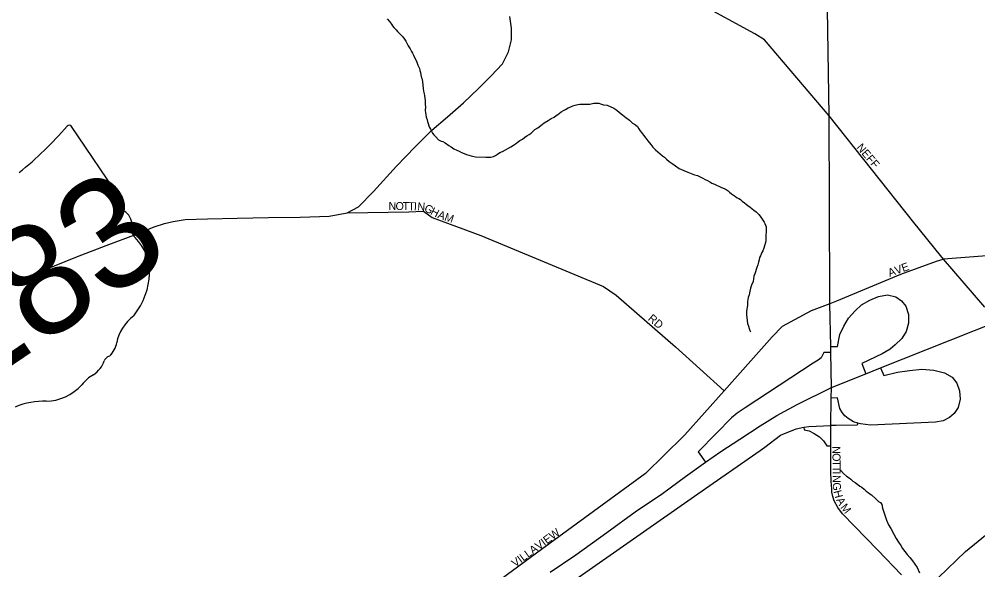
# Model space of a CAD drawing. Extents: x 2139079 to 2262683, y 1235796 to 1334992.
# Drawn here: x 2223564 to 2229551, y 1303635 to 1307072 of the extents above; entities that cross this region are included whole.
import ezdxf

# ---------------------------------------------------------------- set-up
doc = ezdxf.new("R2010")
doc.units = 0
for name, color, linetype in [('GM_X_City_Street', 7, 'Continuous'), ('GM_X_City_Street_Text', 7, 'Continuous'), ('GM_X_Interchange_Ramps', 7, 'Continuous'), ('GM_X_Interstate_Route', 7, 'Continuous'), ('GM_X_Minor_River', 7, 'Continuous'), ('GM_X_State_Route', 7, 'Continuous'), ('GM_X_State_Shield', 7, 'Continuous')]:
    doc.layers.add(name, color=color, linetype=linetype)

msp = doc.modelspace()

# ---------------------------------------------------------------- linework, layer by layer
at = {"layer": 'GM_X_City_Street'}
for points in [[(2228627.4, 1305337.6), (2228622.6, 1306468.3), (2228588, 1308737.8)], [(2229151.8, 1305804), (2228622.6, 1306468.3), (2228218.5, 1306943.9), (2228158.5, 1306979.9), (2227102.5, 1307556.5), (2226602.2, 1307841.3)], [(2231294.5, 1306314.6), (2230784.6, 1305955.9), (2230638.5, 1305853.4), (2230457.2, 1305736.7), (2230340.9, 1305675.6), (2230212.8, 1305648.7), (2229939.3, 1305624.3), (2229634.8, 1305597.1), (2229335.6, 1305573.3), (2229331.3, 1305572)], [(2225612.1, 1305864.1), (2225997.3, 1305869.4), (2226087.3, 1305872.9)], [(2226087.3, 1305872.9), (2226089.9, 1305873), (2226143.3, 1305834.3), (2226448.2, 1305722.8), (2227212.5, 1305403.8), (2227292.2, 1305349.3), (2227663.7, 1305026.1), (2227966.7, 1304753.5)], [(2229317.2, 1305596.4), (2229151.8, 1305804)], [(2229594.4, 1305274.8), (2229335.6, 1305573.3), (2229317.2, 1305596.4)], [(2229331.3, 1305572), (2229291.4, 1305560.5), (2229067, 1305477.9), (2228668.4, 1305312.9)], [(2228632.6, 1304536.4), (2228635.1, 1304707.6), (2228636.1, 1304773.8), (2228632.6, 1304992.1), (2228632, 1305028.5), (2228627.6, 1305296), (2228627.4, 1305337.6)], [(2228668.4, 1305312.9), (2228627.6, 1305296), (2228510.9, 1305252.2), (2228328.5, 1305153.2), (2228266.1, 1305089.2), (2227966.7, 1304753.5)], [(2229193.8, 1303478.3), (2229473.2, 1303749.8), (2230411, 1304512.8), (2231077.9, 1305045.6)], [(2227966.7, 1304753.5), (2227721, 1304477.4)], [(2228191, 1304380.9), (2228221.1, 1304401.9), (2228319.6, 1304475), (2228415.4, 1304514.4), (2228463.9, 1304526.7), (2228494.6, 1304530.7), (2228632.6, 1304536.4)], [(2228633.4, 1304246.7), (2228631.9, 1304320.6), (2228632.2, 1304408.5), (2228632.6, 1304536.4)], [(2227721, 1304477.4), (2227713.4, 1304468.9), (2227475.6, 1304235.7), (2226826.9, 1303762.5), (2226573.7, 1303576.5), (2226301.9, 1303399.3), (2226018.4, 1303234), (2225663.9, 1303080.5), (2225061.4, 1302832.6), (2224423.2, 1302561), (2224116.1, 1302431.2), (2223903.5, 1302360.3), (2223820.7, 1302336.7), (2223611.1, 1302336.8)], [(2224581.8, 1302339.7), (2225814.8, 1302839.9), (2226126.7, 1302972.1), (2226328.4, 1303062.8), (2226638.7, 1303296), (2227803.3, 1304110.5), (2228191, 1304380.9)], [(2228638.6, 1304139), (2228634.6, 1304188.9), (2228633.4, 1304246.7)], [(2229073.7, 1303604), (2228926.2, 1303758.5), (2228706.1, 1303984), (2228677, 1304023.6), (2228653.9, 1304065.1), (2228645, 1304093.7), (2228640.1, 1304120.2), (2228638.6, 1304139)]]:
    msp.add_lwpolyline(points, dxfattribs=at)
at = {"layer": 'GM_X_Interchange_Ramps'}
for points in [[(2228632, 1305028.5), (2228675, 1305029.6), (2228689.2, 1305103.8), (2228713.2, 1305156.8), (2228744.1, 1305206.7), (2228784.8, 1305250.8), (2228824.2, 1305288.5), (2228876.3, 1305317.7), (2228930.9, 1305340.2), (2228985.9, 1305351.4), (2229038.5, 1305338.7), (2229074.6, 1305314.1), (2229100.9, 1305280), (2229118.1, 1305229.1), (2229117.4, 1305175.2), (2229103, 1305122), (2229075.2, 1305079), (2229034.9, 1305038.9), (2229003.1, 1305011.6), (2228952.7, 1304983.1), (2228826.5, 1304922.1), (2228852.1, 1304859.6)], [(2228632.6, 1304992.1), (2228588.2, 1304991.1), (2228571.9, 1304958.2), (2228554.4, 1304943.9), (2228523.4, 1304924.6), (2228098.7, 1304645.9), (2228047.8, 1304613.3), (2228012.7, 1304584.8), (2227918, 1304488.9), (2227803.7, 1304371.7), (2227850.6, 1304307.8)], [(2228943.7, 1304896), (2228963, 1304849.2), (2229049.4, 1304868.4), (2229123.8, 1304879.2), (2229201.1, 1304887.3), (2229276.1, 1304881.1), (2229341.8, 1304863.9), (2229389.9, 1304837.9), (2229419.7, 1304799.4), (2229437.3, 1304752.5), (2229439.9, 1304699.9), (2229428.9, 1304648), (2229402.6, 1304611.3), (2229373.5, 1304586.9), (2229333.6, 1304566.1), (2229287.5, 1304556.4), (2228881.6, 1304537.4), (2228819, 1304546.2), (2228800.7, 1304551.1), (2228774.3, 1304558.1), (2228741.2, 1304580.1), (2228719.6, 1304596.8), (2228704.1, 1304617.7), (2228688.9, 1304642.6), (2228674, 1304707.8), (2228635.1, 1304707.6)], [(2228463.9, 1304526.7), (2228467.2, 1304509.3), (2228498.1, 1304502.7), (2228529, 1304487.2), (2228561.1, 1304465.1), (2228586.5, 1304439.7), (2228607.5, 1304408.8), (2228632.2, 1304408.5)], [(2228800.7, 1304551.1), (2228797.2, 1304538), (2228665.3, 1304536.7), (2228632.6, 1304536.4)]]:
    msp.add_lwpolyline(points, dxfattribs=at)
at = {"layer": 'GM_X_Interstate_Route'}
msp.add_lwpolyline([(2226880.9, 1303621.7), (2227040.4, 1303729.2), (2227233.7, 1303869), (2227411, 1303996.7), (2227582.4, 1304112.3), (2227725.8, 1304217.7), (2227850.6, 1304307.8), (2227947, 1304373.8), (2228064.6, 1304450.9), (2228192.2, 1304534), (2228295.9, 1304599), (2228421.6, 1304668.1), (2228636.1, 1304773.8), (2228852.1, 1304859.6), (2228943.7, 1304896), (2229671.9, 1305185.4)], dxfattribs=at)
at = {"layer": 'GM_X_Minor_River'}
for points in [[(2225862.6, 1307074.5), (2225877, 1307056.7), (2225889.4, 1307040.9), (2225895.6, 1307030.9)], [(2225895.6, 1307030.9), (2225903.8, 1307021.1), (2225918.2, 1307005.3), (2225926.4, 1306995.4), (2225936.7, 1306985.5), (2225947, 1306973.7), (2225959.3, 1306961.9), (2225969.6, 1306948), (2225979.9, 1306934.1), (2225994.5, 1306906.3), (2226005, 1306886.4), (2226013.3, 1306870.5), (2226019.6, 1306860.6), (2226025.9, 1306846.6), (2226032.2, 1306832.7), (2226040.5, 1306818.8), (2226046.8, 1306802.8), (2226053.2, 1306784.9), (2226063.7, 1306765), (2226066, 1306751), (2226070.2, 1306739), (2226072.5, 1306725), (2226076.9, 1306707), (2226081.1, 1306697), (2226085.8, 1306663), (2226086.3, 1306638.9), (2226088.7, 1306622.8), (2226093, 1306606.9), (2226095.3, 1306592.8), (2226097.6, 1306578.8), (2226099.9, 1306564.8), (2226100.1, 1306554.8), (2226100.4, 1306540.7), (2226100.8, 1306522.6), (2226099.1, 1306504.5), (2226101.5, 1306488.5), (2226103.7, 1306476.5), (2226106, 1306460.4), (2226112.4, 1306444.5), (2226114.6, 1306434.5), (2226118.9, 1306420.5), (2226123.2, 1306406.5), (2226127.4, 1306396.6), (2226133.7, 1306384.6), (2226140, 1306372.7), (2226146.2, 1306360.8), (2226154.5, 1306350.9), (2226166.8, 1306337.1), (2226183.2, 1306319.3), (2226199.5, 1306311.6), (2226209.6, 1306307.8), (2226223.8, 1306300), (2226248.2, 1306284.4), (2226262.5, 1306274.6), (2226278.8, 1306262.9), (2226297, 1306255.2), (2226311.2, 1306247.4), (2226327.4, 1306239.7), (2226343.6, 1306234), (2226357.8, 1306228.3), (2226371.9, 1306222.5), (2226386.1, 1306218.8), (2226396.2, 1306216.9), (2226414.3, 1306213.3), (2226478.6, 1306210.5), (2226496.7, 1306210.8), (2226510.7, 1306211.1), (2226526.7, 1306215.4), (2226538.6, 1306221.7), (2226550.5, 1306230), (2226566.4, 1306240.3), (2226582.3, 1306246.6), (2226602.2, 1306257.1), (2226616, 1306265.4), (2226633.9, 1306275.8), (2226651.8, 1306286.2), (2226663.6, 1306294.4), (2226673.5, 1306302.7), (2226691.3, 1306315.1), (2226707.2, 1306323.4), (2226719.1, 1306333.7), (2226734.9, 1306344), (2226748.8, 1306352.3), (2226760.7, 1306360.6), (2226770.6, 1306368.8), (2226784.3, 1306383.1), (2226802.2, 1306393.5), (2226822, 1306408), (2226843.7, 1306424.5), (2226867.5, 1306439), (2226887.3, 1306451.4), (2226905.2, 1306459.8), (2226917.1, 1306470.1), (2226929, 1306476.3), (2226948.7, 1306492.8), (2226962.6, 1306501.1), (2226976.5, 1306509.4), (2226992.4, 1306517.8), (2227008.3, 1306524.1), (2227022.3, 1306530.4), (2227036.2, 1306534.7)], [(2227036.2, 1306534.7), (2227052.2, 1306539), (2227066.2, 1306541.3), (2227082.3, 1306541.6), (2227092.3, 1306541.8), (2227102.4, 1306542), (2227118.4, 1306542.3), (2227128.4, 1306542.5), (2227152.5, 1306547), (2227170.5, 1306547.3), (2227184.6, 1306547.6), (2227194.7, 1306543.8), (2227212.9, 1306538.1), (2227237, 1306534.6), (2227277.6, 1306517.2), (2227295.9, 1306503.5), (2227312.3, 1306489.8), (2227332.7, 1306474.1), (2227353.1, 1306458.4), (2227375.5, 1306442.8), (2227393.9, 1306423.1), (2227412.2, 1306413.4), (2227426.5, 1306401.6), (2227434.8, 1306387.7), (2227441, 1306377.8), (2227451.4, 1306363.9), (2227463.7, 1306348.1), (2227478.2, 1306330.3), (2227490.6, 1306312.4), (2227509.1, 1306290.7), (2227521.5, 1306272.9), (2227537.9, 1306257.1), (2227552.2, 1306243.3), (2227566.5, 1306231.5), (2227580.8, 1306219.8), (2227595.1, 1306210), (2227607.4, 1306198.2), (2227623.7, 1306184.4), (2227642.1, 1306170.7), (2227662.4, 1306157.1), (2227684.9, 1306139.4), (2227715.2, 1306127.9), (2227739.6, 1306116.3), (2227759.8, 1306108.7), (2227782, 1306101.1), (2227800.2, 1306095.4), (2227816.5, 1306087.7), (2227832.7, 1306080), (2227848.9, 1306072.3), (2227863.1, 1306064.5), (2227877.3, 1306056.7), (2227889.5, 1306048.9), (2227905.7, 1306043.2), (2227950.3, 1306022), (2227966.5, 1306014.3), (2227978.7, 1306008.5), (2227990.9, 1306000.7), (2228001.1, 1305992.8), (2228013.4, 1305983), (2228025.6, 1305973.2), (2228037.8, 1305965.4), (2228048, 1305957.6), (2228058.1, 1305953.8), (2228068.3, 1305945.9), (2228078.6, 1305936.1), (2228092.8, 1305926.3), (2228105.1, 1305916.5), (2228117.3, 1305906.7), (2228127.5, 1305900.9), (2228141.8, 1305889.1), (2228152, 1305879.2), (2228166.3, 1305869.5), (2228182.7, 1305853.7), (2228191, 1305841.8), (2228199.2, 1305829.9), (2228207.5, 1305818), (2228215.8, 1305806.1), (2228220, 1305796.2), (2228224.2, 1305786.2), (2228228.4, 1305776.2), (2228228.7, 1305764.2), (2228229.1, 1305742.1), (2228227.5, 1305726), (2228227.7, 1305716), (2228227.9, 1305705.9), (2228226.2, 1305687.8), (2228224.4, 1305677.7), (2228218.8, 1305657.5), (2228215.1, 1305643.4), (2228207.4, 1305627.2), (2228201.6, 1305615), (2228194, 1305594.8), (2228188.2, 1305584.6), (2228184.5, 1305570.5), (2228180.7, 1305556.3), (2228177.1, 1305538.2), (2228171.4, 1305522), (2228158.1, 1305483.6), (2228152.4, 1305467.4), (2228147.1, 1305435.1), (2228137.5, 1305412.9)], [(2228137.5, 1305412.9), (2228131.9, 1305392.7), (2228126.2, 1305374.5), (2228122.7, 1305352.3), (2228117, 1305334.1), (2228115.2, 1305322), (2228113.5, 1305309.9), (2228111.7, 1305297.8), (2228112, 1305285.8), (2228110.2, 1305273.7), (2228108.4, 1305261.6), (2228106.7, 1305247.5), (2228106.9, 1305237.5), (2228107.2, 1305225.4), (2228107.5, 1305209.4), (2228109.9, 1305191.3), (2228112.3, 1305173.3), (2228118.6, 1305155.3), (2228123, 1305141.3), (2228127.2, 1305129.4), (2228131.4, 1305121.4)], [(2228693.2, 1304260.3), (2228695.3, 1304254.3), (2228711.7, 1304236.6), (2228730.1, 1304220.9), (2228746.4, 1304209.1), (2228758.6, 1304201.3), (2228770.9, 1304189.5), (2228785.2, 1304179.7), (2228801.5, 1304168), (2228813.7, 1304158.2), (2228825.9, 1304150.4), (2228840.2, 1304138.6), (2228854.5, 1304126.8), (2228866.8, 1304117), (2228877, 1304109.2), (2228887.1, 1304103.3), (2228915.8, 1304075.8), (2228930.2, 1304062), (2228942.3, 1304056.2), (2228950.6, 1304042.3), (2228955.1, 1304020.3), (2228963.7, 1303994.3), (2228972.2, 1303970.4), (2228980.8, 1303944.4), (2228993.4, 1303916.6), (2229007.9, 1303892.7), (2229026.7, 1303858.9), (2229041.3, 1303831.1), (2229055.8, 1303807.3), (2229070.3, 1303787.4), (2229080.8, 1303767.6), (2229095.2, 1303749.7), (2229109.6, 1303731.9), (2229126.1, 1303712.2), (2229142.5, 1303692.4), (2229157, 1303670.6), (2229171.5, 1303648.8), (2229186.2, 1303616.9)]]:
    msp.add_lwpolyline(points, dxfattribs=at)
at = {"layer": 'GM_X_State_Route'}
for points in [[(2226431.8, 1306640.2), (2226510.5, 1306716.7), (2226581.6, 1306792.6), (2226620.5, 1306867.3), (2226639, 1306943.1), (2226639, 1307015.8), (2226627.7, 1307088.5)], [(2225612.1, 1305864.1), (2225683.8, 1305900.4), (2225776.7, 1305996.4), (2225921.2, 1306155.5), (2226036.5, 1306274.7), (2226141.8, 1306379.8), (2226239.3, 1306462.7), (2226338.8, 1306549.7), (2226431.8, 1306640.2)], [(2223470, 1305409.2), (2223707.7, 1305501.3), (2223929.5, 1305591.2), (2224107.3, 1305658.7), (2224297.1, 1305730.3), (2224407, 1305775.2), (2224470.9, 1305797.7), (2224525, 1305810.2), (2224601.1, 1305820.8), (2224741.4, 1305825.8), (2224925.7, 1305829.2), (2225122.1, 1305834.7), (2225318.6, 1305836.2), (2225500.9, 1305842.6), (2225612.1, 1305864.1)]]:
    msp.add_lwpolyline(points, dxfattribs=at)
at = {"layer": 'GM_X_State_Shield'}
for p, q in [((2224201.5, 1305944.6), (2223891.6, 1306402.2)), ((2224201.3, 1305944.6), (2224201.5, 1305944.6))]:
    msp.add_line(p, q, dxfattribs=at)
for centre, major_axis, start_param, end_param in [((2222585.1, 1307225.6), (1527.9, 1034.9), 4.814394, 5.042369), ((2223874.3, 1306393.3), (16, 10.9), 6.141152, 7.989035), ((2224185.6, 1305931.2), (17.2, 11.6), 5.05454, 6.418171), ((2224220.6, 1305908.5), (24.8, 16.8), 1.883978, 3.671073), ((2224101.9, 1305743.7), (149, 100.9), 5.934695, 6.695948), ((2224388.7, 1305792), (108.4, 73.4), 2.387724, 3.262537), ((2223943.1, 1305405.2), (382.2, 258.9), 5.101752, 6.440018), ((2224408.9, 1305064.5), (209.3, 141.8), 1.647645, 2.488434), ((2224034.7, 1305045.7), (123.5, 83.6), 4.937069, 5.64225), ((2223967.2, 1304948.2), (116.7, 79.1), 4.691044, 5.507374), ((2224130.2, 1304934.9), (32.9, 22.3), 1.147584, 2.315152), ((2224111.7, 1304700.4), (180, 121.9), 1.495662, 1.94098), ((2223780.3, 1304917.1), (219.1, 148.4), 4.026481, 4.996735), ((2223636, 1304326), (345.2, 233.8), 0.823519, 1.323587)]:
    msp.add_ellipse(centre, major_axis=major_axis, ratio=0.8, start_param=start_param, end_param=end_param, dxfattribs=at)

# ---------------------------------------------------------------- texts
at = {"layer": 'GM_X_City_Street_Text'}
for s, rotation, p in [('NEFF', 310.23863, (2228790.4, 1306270.2)), ('N', 359.08195, (2225870.3, 1305882)), ('O', 359.11446, (2225914.3, 1305881.3)), ('T', 359.09842, (2225958.3, 1305880.6)), ('T', 359.07111, (2225993.5, 1305880.1)), ('I', 359.13153, (2226028.8, 1305879.5)), ('N', 356.26007, (2226050.1, 1305879.2)), ('G', 330.97087, (2226088.5, 1305878)), ('H', 332.57371, (2226128.3, 1305855.9)), ('A', 339.89096, (2226173.7, 1305832.8)), ('M', 340.56472, (2226215.7, 1305817.5)), ('AVE', 19.64393, (2229000.2, 1305463.5)), ('RD', 319.39614, (2227487, 1305197.8)), ('N', 270.08745, (2228643.1, 1304407.4)), ('O', 270.08288, (2228643.2, 1304363.4)), ('T', 270.08396, (2228643.3, 1304319.4)), ('T', 270.09545, (2228643.3, 1304284.2)), ('I', 270.08742, (2228643.4, 1304249)), ('N', 270.5895, (2228643.4, 1304226.5)), ('G', 274.32674, (2228644, 1304179)), ('H', 284.84551, (2228649, 1304125.2)), ('A', 297.62805, (2228664.7, 1304071.4)), ('M', 307.47497, (2228690.1, 1304024.5)), ('VILLAVIEW', 36.13634, (2226661.4, 1303649.4))]:
    msp.add_text(s, height=50, rotation=rotation, dxfattribs=at).set_placement(p)
at = {"layer": 'GM_X_State_Shield'}
msp.add_text('283', height=696.1, rotation=34.11139, dxfattribs=at).set_placement((2223248.2, 1304726.6))

doc.saveas('drawing.dxf')
